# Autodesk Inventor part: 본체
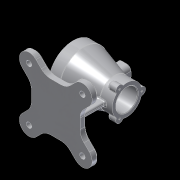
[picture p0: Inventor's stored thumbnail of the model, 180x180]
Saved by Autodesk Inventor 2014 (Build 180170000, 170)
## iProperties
Created: 2018-03
Part Number: 본체
Material: 알루미늄 6061
Document SubType Name: Modeling
Designer: user
Density: 2.71 g/cm^3
Appearance: 알루미늄 - 평지
Mass: 1015 g
Surface Area: 853.881 cm^2
Volume: 374.54 cm^3
Author: user
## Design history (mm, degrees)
sketch "스케치1"
  geometry: L1 (-45, 45)-(-19.544, 45); L2 (45, 45)-(45, 19.544); L3 (45, -45)-(19.544, -45); L4 (-45, -45)-(-45, -19.544); L5 (-45, 45)-(45, -45); L6 (45, 45)-(-45, -45); L7 (49.497, -49.497)-(-49.497, 49.497); L8 (49.497, -49.497)-(-49.497, 49.497); L9 (62.225, -36.77)-(45, -19.544); L10 (-62.225, 36.77)-(-45, 19.544); L11 (49.497, 49.497)-(-49.497, -49.497); L12 (49.497, 49.497)-(-49.497, -49.497); L13 (36.77, 62.225)-(19.544, 45); L14 (-36.77, -62.225)-(-19.544, -45); L15 (19.544, -45)-(-19.544, -45); L16 (45, -19.544)-(45, -45); L17 (45, 19.544)-(45, -19.544); L18 (19.544, 45)-(45, 45); L19 (45, 19.544)-(62.225, 36.77); L20 (19.544, -45)-(36.77, -62.225); L21 (-19.544, -45)-(-45, -45); L22 (-45, -19.544)-(-45, 19.544); L23 (-45, -19.544)-(-62.225, -36.77); L24 (-45, 19.544)-(-45, 45); L25 (-19.544, 45)-(-36.77, 62.225); L26 (-19.544, 45)-(19.544, 45); C1 r 5 at (49.497, -49.497); C2 r 5 at (-49.497, 49.497); C3 r 5 at (-49.497, -49.497); C4 r 5 at (49.497, 49.497); A1 r 70 centre (0, 0) between (49.497, -49.497) and (-49.497, 49.497); A2 r 18 centre (49.497, -49.497) between (36.77, -62.225) and (62.225, -36.77); A3 r 18 centre (-49.497, 49.497) between (-36.77, 62.225) and (-62.225, 36.77); A4 r 18 centre (49.497, 49.497) between (62.225, 36.77) and (36.77, 62.225); A5 r 18 centre (-49.497, -49.497) between (-62.225, -36.77) and (-36.77, -62.225); 3 further points
  constraints: 56 end point, 26 parallel, 16 tangent, 13 point on circle, 10 perpendicular, 9 centre point, 6 coincident, 5 midpoint, 3 horizontal, 1 collinear, 1 point on line
  dimensions: "d0" = 140 diameter of A1; "d1" = 90 distance of L2.start L3.start; "d2" = 90 distance of L3.start L4.start; "d4" = 10 diameter of C2; "d5" = 10 diameter of C1; "d7" = 10 diameter of C4; "d8" = 10 diameter of C3; "d9" = 36 distance between parallel lines of L20 L9; "d10" = 36 distance between parallel lines of L23 L14
extrude "돌출1" new body sketch "스케치1" distance "d11" = 12; taper "d12" = 0 deg
fillet "모깎기1" dims "d13" = 25
chamfer "모따기1" distance "d14" = 3; stored, may be unused: second distance "d15" = 2, angle "d16" = 45 deg
sketch "스케치2"
  geometry: L1 (-50, 82)-(50, 82); L2 (-49, 117)-(-30, 117); L3 (-27, 114)-(-27, 111); L4 (-24, 108)-(17, 108); L5 (20, 105)-(20, 105); L6 (23, 102)-(49, 102); L7 (50, 103)-(50, 109.5); L8 (50, 109.5)-(27, 109.5); L9 (27, 109.5)-(-30, 127); L10 (-30, 127)-(-50, 127); L11 (-50, 127)-(-50, 118); L12 (49, 102)-(50, 103); L13 (-49, 117)-(-50, 118); A1 r 3 centre (-30, 114) between (-27, 114) and (-30, 117); A2 r 3 centre (-24, 111) between (-27, 111) and (-24, 108); A3 r 3 centre (17, 105) between (20, 105) and (17, 108); A4 r 3 centre (23, 105) between (20, 105) and (23, 102); 6 further points
  constraints: 26 end point, 12 point on line, 8 parallel, 8 point on circle, 8 tangent, 4 centre point, 3 equal radius, 1 horizontal, 1 perpendicular
  dimensions: "d18" = 82 distance from line of L1 point (0, 0); "d19" = 100 distance of L1.start L1.end; "d20" = 50 horizontal distance of point (0, 0) L1.start; "d21" = 70 diameter of L2 L1; "d22" = 52 diameter of L4 L1; "d23" = 40 diameter of L6 L1; "d24" = 55 diameter of L8 L1; "d25" = 90 diameter of L10 L1; "d26" = 20 distance of L9.end L10.end; "d27" = 23 distance of point (-50, 117) point (-27, 117); "d28" = 47 distance of point (-27, 108) point (20, 108); "d29" = 77 distance from line of L11 L8.end; "d30" = 3 radius of A1; "d31" = 1 distance of L6.end point (50, 102); "d32" = 1 distance of L7.start point (50, 102) (= d31); "d34" = 1 distance of L2.start point (-50, 117); "d35" = 1 distance of L11.end point (-50, 117) (= d34)
revolve "회전1" sketch "스케치2" stored, may be unused: angle "d33" = 90 deg
sketch "스케치3"
  geometry: C1 r 45 at (0, 0) reference; 2 further points
  constraints: 1 vertical alignment
  dimensions: "d36" = 40 distance of C1.centre point (0, 40)
hole "구멍1" sketch "스케치3" at (0, 40) diameter "d37" = 3.242; stored, may be unused: countersink angle "d41" = 90 deg, drill point angle "d43" = 118 deg; dims "d38" = 9, "d39" = 4, "d40" = 2, "d42" = 11
sketch "스케치4"
  geometry: C1 r 21 at (0, 0) reference; A1 r 27.5 centre (0, 0) between (0, 27.5) and (6.943, 26.609) reference; A2 r 7 centre (0, 27.5) between (6.943, 26.609) and (-6.943, 26.609); 1 further point
  constraints: 5 point on circle, 1 centre point, 1 vertical alignment
  dimensions: "d47" = 14 diameter of A2
extrude "돌출2" join sketch "스케치4" distance "d48" = 15; taper "d49" = 0 deg
hole "구멍2" diameter "d52" = 3.242; stored, may be unused: countersink angle "d56" = 90 deg, drill point angle "d58" = 118 deg; dims "d50" = 10, "d51" = 10, "d53" = 9, "d54" = 4, "d55" = 2, "d57" = 11
fillet "모깎기2" dims "d59" = 1, "d60" = 3
fillet "모깎기3" dims "d64" = 3
node "작업 평면1"
sketch "스케치5"
  geometry: L1 (-4.5, 12.5)-(4.5, 12.5); L2 (12.5, 4.5)-(12.5, -4.5); L3 (4.5, -12.5)-(-4.5, -12.5); L4 (-12.5, -4.5)-(-12.5, 4.5); L5 (-12.5, 12.5)-(12.5, -12.5); L6 (12.5, 12.5)-(-12.5, -12.5); A1 r 8 centre (-4.5, 4.5) between (-4.5, 12.5) and (-12.5, 4.5); A2 r 8 centre (4.5, 4.5) between (12.5, 4.5) and (4.5, 12.5); A3 r 8 centre (4.5, -4.5) between (4.5, -12.5) and (12.5, -4.5); A4 r 8 centre (-4.5, -4.5) between (-12.5, -4.5) and (-4.5, -12.5); 1 further point
  constraints: 12 end point, 8 point on circle, 8 point on line, 8 tangent, 4 centre point, 3 equal radius, 2 midpoint, 2 parallel, 1 horizontal, 1 perpendicular
  dimensions: "d66" = 25 distance of L6.start L5.end; "d67" = 25 distance of L5.end L6.end; "d68" = 8 radius of A1
extrude "돌출3" join sketch "스케치5" stored distance "d69" = 12; taper "d70" = 0 deg
sketch "스케치6"
  geometry: L1 (4.5, -7.5)-(-4.5, -7.5); L2 (-7.5, -4.5)-(-7.5, 4.5); L3 (-4.5, 7.5)-(4.5, 7.5); L4 (7.5, 4.5)-(7.5, -4.5); L5 (7.5, -7.5)-(-7.5, 7.5); L6 (-7.5, -7.5)-(7.5, 7.5); A1 r 3 centre (-4.5, 4.5) between (-4.5, 7.5) and (-7.5, 4.5); A2 r 3 centre (4.5, 4.5) between (7.5, 4.5) and (4.5, 7.5); A3 r 3 centre (4.5, -4.5) between (4.5, -7.5) and (7.5, -4.5); A4 r 3 centre (-4.5, -4.5) between (-7.5, -4.5) and (-4.5, -7.5); 1 further point
  constraints: 12 end point, 8 point on circle, 8 point on line, 8 tangent, 4 centre point, 3 equal radius, 2 midpoint, 2 parallel, 1 horizontal, 1 perpendicular
  dimensions: "d71" = 15 distance of L6.start L5.end; "d72" = 15 distance of L5.end L6.end; "d73" = 3 radius of A1
extrude "돌출4" cut sketch "스케치6" stored distance "d74" = 12; taper "d75" = 0 deg
chamfer "모따기2" distance "d76" = 1; stored, may be unused: second distance "d77" = 2, angle "d78" = 45 deg
fillet "모깎기4" dims "d79" = 1
sketch "스케치7"
  geometry: L1 (37, -4)-(-37, -4); L2 (-37, -4)-(-37, 4); L3 (-37, 4)-(37, 4); L4 (37, 4)-(37, -4); L5 (37, -4)-(-37, 4); L6 (-37, -4)-(37, 4); 1 further point
  constraints: 12 end point, 2 midpoint, 2 parallel, 1 horizontal, 1 perpendicular
  dimensions: "d80" = 8 distance of L1.end L2.end; "d81" = 74 distance of L1.start L1.end
extrude "돌출5" join sketch "스케치7" stored distance "d82" = 0; taper "d83" = 0 deg
sketch "스케치8"
  geometry: L1 (4, -24)-(-4, -24); L2 (-4, -24)-(-4, 24); L3 (-4, 24)-(4, 24); L4 (4, 24)-(4, -24); L5 (4, -24)-(-4, 24); L6 (-4, -24)-(4, 24); 1 further point
  constraints: 12 end point, 2 midpoint, 2 parallel, 1 horizontal, 1 perpendicular
  dimensions: "d84" = 8 distance of L2.end L3.end; "d85" = 48 distance of L1.end L2.end
extrude "돌출6" join sketch "스케치8" stored distance "d86" = 12; taper "d87" = 0 deg
feature "면 기울기1" dims angle "d88" = 5 deg
fillet "모깎기5" dims "d89" = 3
fillet "모깎기6" dims "d90" = 3
sketch "스케치9"
  geometry: L1 (45, -9.189)-(45, 9.189) reference; 2 further points
  constraints: 1 other
  dimensions: "d91" = 35 distance of point (0, -35) point (0, 0); "d92" = 45 distance from line of point (0, -35) L1
feature "엠보싱1" sketch "스케치9" dims "d0" = 140, "d1" = 90, "d2" = 90, "d4" = 10, "d5" = 10, "d7" = 10, "d8" = 10, "d9" = 36, "d10" = 36, "d93" = 0.5, "d94" = 0
node "솔리드1"
pattern_circular "원형 패턴1" dims angle "d45" = 360 deg
pattern_circular "원형 패턴2" dims "d62" = 360 deg
other parameters: "d65" = 127
